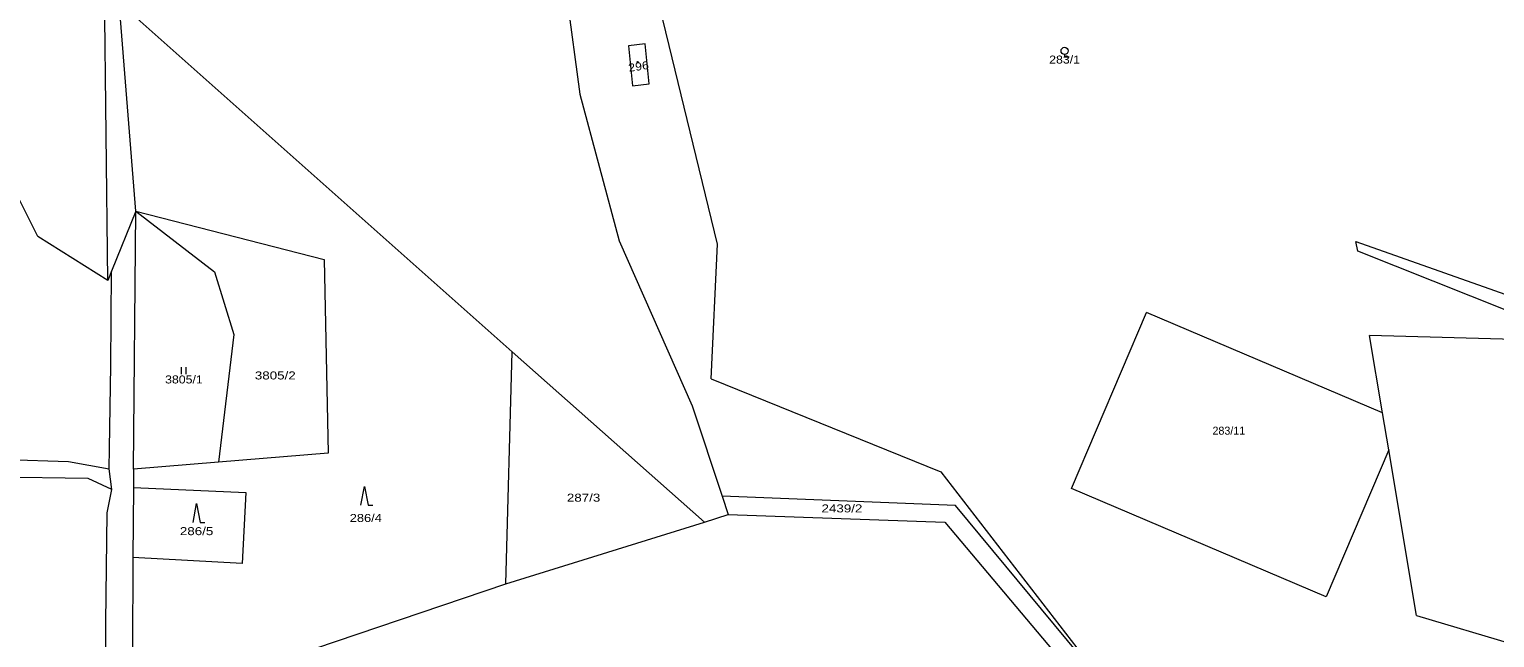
# Model space of a CAD drawing. Extents: x -590528 to -586543, y -1119609 to -1116685.
# Drawn here: x -589346.9 to -589035.6, y -1118332.6 to -1118203.4 of the extents above; entities that cross this region are included whole.
import ezdxf
from ezdxf.enums import TextEntityAlignment as Align

# ---------------------------------------------------------------- set-up
doc = ezdxf.new("R2010")
doc.units = 0
doc.header["$LTSCALE"] = 0.68
for name, color, linetype, lineweight in [('1', 7, 'Continuous', 13), ('3', 7, 'Continuous', 13), ('6', 7, 'Continuous', 13)]:
    doc.layers.add(name, color=color, linetype=linetype, lineweight=lineweight)

msp = doc.modelspace()

# ---------------------------------------------------------------- linework, layer by layer
at = {"layer": '1'}
for p, q in [((-589244.54, -1118110.78), (-589229.96, -1118217.17)), ((-589244.38, -1118271.92), (-589327.84, -1118197.76)), ((-589345.1, -1118247.45), (-589351.94, -1118233.83)), ((-589330.24, -1118256.76), (-589345.1, -1118247.45)), ((-589329.45, -1118254.79), (-589330.24, -1118256.76)), ((-589125.5, -1118300.97), (-589109.59, -1118263.57)), ((-589059.43, -1118284.91), (-589109.59, -1118263.57)), ((-589303.47, -1118268.23), (-589306.78, -1118295.36)), ((-589059.43, -1118284.91), (-589062.19, -1118268.47)), ((-589016.64, -1118269.69), (-589062.19, -1118268.47)), ((-589245.69, -1118321.18), (-589244.38, -1118271.92)), ((-589244.38, -1118271.92), (-589203.5, -1118308.1)), ((-589202.1, -1118277.65), (-589153.28, -1118297.42)), ((-589058.11, -1118292.75), (-589071.4, -1118323.98)), ((-589329.42, -1118301.15), (-589329.98, -1118296.79)), ((-589153.28, -1118297.42), (-589114.64, -1118347.32)), ((-589324.8, -1118300.73), (-589300.97, -1118301.81)), ((-589300.97, -1118301.81), (-589301.73, -1118316.9)), ((-589150.17, -1118304.55), (-589199.75, -1118302.57)), ((-589071.4, -1118323.98), (-589125.5, -1118300.97)), ((-589203.5, -1118308.1), (-589198.46, -1118306.45)), ((-589198.46, -1118306.45), (-589152.4, -1118308.08)), ((-589114.64, -1118347.32), (-589150.17, -1118304.55)), ((-589245.69, -1118321.18), (-589203.5, -1118308.1)), ((-589152.4, -1118308.08), (-589103.56, -1118366.12)), ((-589301.73, -1118316.9), (-589324.91, -1118315.62)), ((-589326.04, -1118348.34), (-589245.69, -1118321.18))]:
    msp.add_line(p, q, dxfattribs=at)
for points in [[(-589202.1, -1118277.65), (-589200.72, -1118249.03), (-589221.94, -1118161.68), (-589233.21, -1118141.42)], [(-589330.24, -1118256.76), (-589330.95, -1118194.68), (-589310.37, -1118158.41)], [(-589324.34, -1118242.06), (-589327.84, -1118197.76), (-589306.62, -1118160.25)], [(-589229.96, -1118217.17), (-589221.63, -1118248.33), (-589206.13, -1118283.41)], [(-589324.77, -1118296.83), (-589324.34, -1118242.06), (-589329.45, -1118254.79)], [(-589324.34, -1118242.06), (-589284.26, -1118252.28), (-589283.44, -1118293.46), (-589306.78, -1118295.36), (-589324.77, -1118296.83), (-589324.8, -1118300.73), (-589324.91, -1118315.62), (-589325.05, -1118335.4)], [(-589324.34, -1118242.06), (-589307.59, -1118254.91), (-589303.47, -1118268.23)], [(-589016.64, -1118269.69), (-589064.7, -1118250.56), (-589065.09, -1118248.48), (-589016.81, -1118265.57)], [(-589375.98, -1118294.62), (-589351.74, -1118294.77), (-589338.64, -1118295.23), (-589329.98, -1118296.79), (-589329.91, -1118292.36), (-589329.64, -1118274.9), (-589329.45, -1118254.79)], [(-589206.13, -1118283.41), (-589199.75, -1118302.57), (-589198.46, -1118306.45)], [(-589052.2, -1118327.94), (-589058.11, -1118292.75), (-589059.43, -1118284.91)], [(-589330.68, -1118329.38), (-589330.39, -1118306.1), (-589329.42, -1118301.15), (-589334.45, -1118298.8), (-589392.94, -1118297.95)], [(-589052.2, -1118327.94), (-589031.78, -1118334), (-589013.6, -1118339.4)], [(-589338.39, -1118371.5), (-589337.84, -1118365.42), (-589334.45, -1118354.46), (-589331.95, -1118348.76), (-589330.94, -1118343.98), (-589330.65, -1118335.55), (-589330.68, -1118329.38)]]:
    msp.add_lwpolyline(points, dxfattribs=at)
msp.add_lwpolyline([(-589219.63, -1118206.96), (-589218.81, -1118215.42), (-589215.25, -1118214.97), (-589216.07, -1118206.52)], close=True, dxfattribs=at)
at = {"layer": '6'}
for p, q in [((-589314.59, -1118276.69), (-589314.59, -1118275.19)), ((-589313.59, -1118276.69), (-589313.59, -1118275.19))]:
    msp.add_line(p, q, dxfattribs=at)
for points in [[(-589126.99, -1118208.75), (-589126.99, -1118209.25), (-589125.99, -1118209.25)], [(-589276.48, -1118304.52), (-589275.73, -1118300.52), (-589274.98, -1118304.52), (-589273.98, -1118304.52)], [(-589312.15, -1118308.16), (-589311.4, -1118304.16), (-589310.65, -1118308.16), (-589309.65, -1118308.16)]]:
    msp.add_lwpolyline(points, dxfattribs=at)
for centre, radius in [((-589126.99, -1118208), 0.75), ((-589217.7001, -1118210.4002), 0.1172)]:
    msp.add_circle(centre, radius, dxfattribs=at)

# ---------------------------------------------------------------- texts
at = {"layer": '3', "width": 1.15}
msp.add_text('296', height=1.7, rotation=8.594, dxfattribs=at).set_placement((-589217.3735, -1118212.1509), align=Align.CENTER)
at = {"layer": '3'}
for s, width, p in [('283/1', 1.15, (-589126.9905, -1118210.7)), ('3805/1', 1.15, (-589314.0905, -1118278.64)), ('3805/2', 1.25, (-589294.6805, -1118277.79)), ('287/3', 1.25, (-589229.18, -1118303.75)), ('286/4', 1.2, (-589275.4505, -1118308.06)), ('2439/2', 1.25, (-589174.2905, -1118306.03)), ('286/5', 1.25, (-589311.4, -1118310.86))]:
    msp.add_text(s, height=1.7, dxfattribs=dict(at, width=width)).set_placement(p, align=Align.CENTER)
msp.add_text('283/11', height=1.7, dxfattribs=at).set_placement((-589092.0905, -1118289.52), align=Align.CENTER)

doc.saveas('drawing.dxf')
